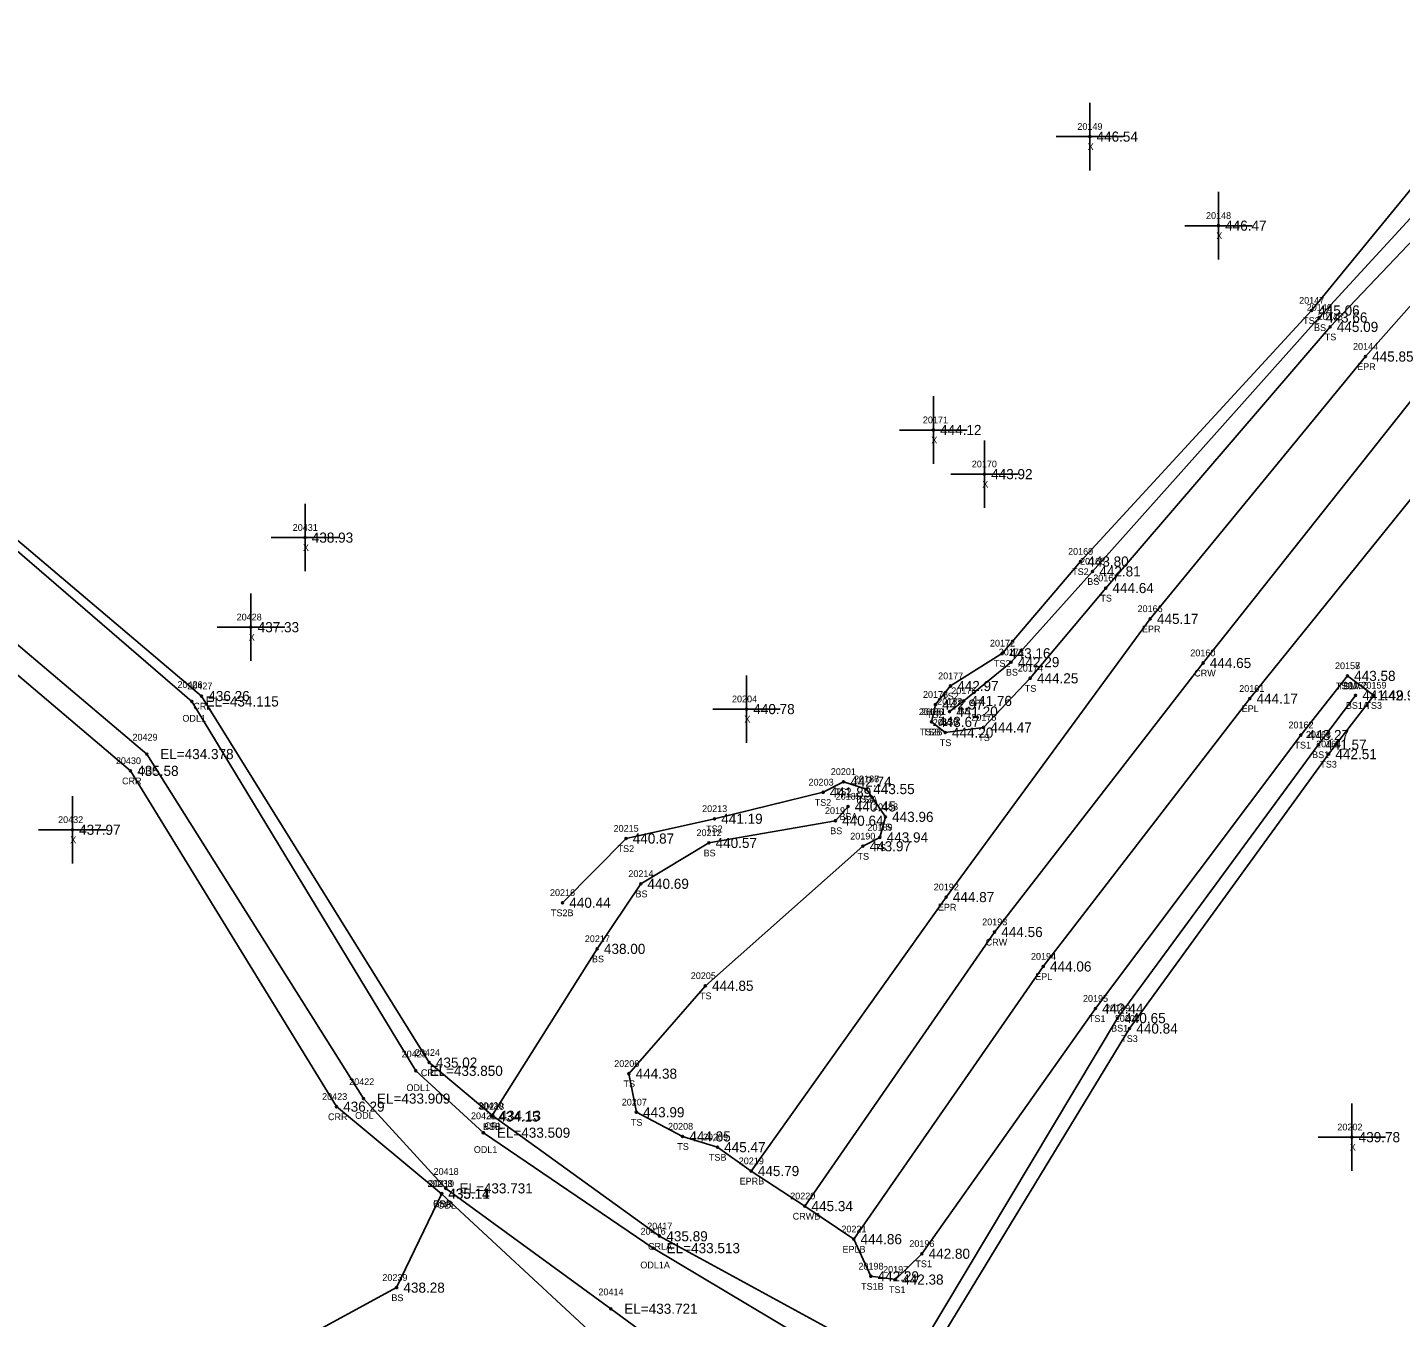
# Model space of a CAD drawing. Extents: x 1763022 to 1764007, y 824123 to 825394.
# Drawn here: x 1763375.9 to 1763579.5, y 824815.6 to 825006.9 of the extents above; entities that cross this region are included whole.
import ezdxf

# ---------------------------------------------------------------- set-up
doc = ezdxf.new("R2010")
doc.units = 0
for name, color, linetype in [('RD_DTM_BkLn1', 7, 'Continuous'), ('RD_DTM_BkLn2', 7, 'Continuous'), ('RD_DTM_BkLn_txCode', 7, 'Continuous'), ('RD_EX_H2O', 7, 'Continuous'), ('RD_EX_H2O_txCode', 7, 'Continuous'), ('RD_EX_Misc', 7, 'Continuous'), ('RD_EX_Misc_txCode', 7, 'Continuous'), ('RD_EX_Road', 7, 'Continuous'), ('RD_EX_Road_txCode', 7, 'Continuous'), ('RD_EX_TX_H2O_ELEV', 7, 'Continuous'), ('RD_EX_TX_Misc_ELEV', 7, 'Continuous'), ('RD_EX_TX_Road_ELEV', 7, 'Continuous'), ('RD_HC_Survey_ELEV', 7, 'Continuous'), ('RD_HC_Survey_txCode', 7, 'Continuous'), ('RD_SMD_Locator', 7, 'Continuous')]:
    doc.layers.add(name, color=color, linetype=linetype)

msp = doc.modelspace()

# ---------------------------------------------------------------- linework, layer by layer
at = {"layer": 'RD_DTM_BkLn1'}
msp.add_lwpolyline([(1763957.85, 825358.99), (1763889.22, 825284.86), (1763820.79, 825210.5), (1763751.37, 825137.44), (1763682.52, 825063.34), (1763613.99, 824989.62), (1763581.46, 824952.08), (1763550.2, 824912.66), (1763519.29, 824872.78), (1763491.16, 824832.15)], dxfattribs=at)
at = {"layer": 'RD_DTM_BkLn2'}
for points in [[(1763745.88, 825160.71), (1763743.95, 825161.45), (1763741.33, 825161.23), (1763734.19, 825151.51), (1763667.93, 825076.53), (1763598.29, 825004), (1763566.28, 824964.92), (1763532.04, 824927.7), (1763520.45, 824914.1), (1763512.76, 824909.25), (1763510.52, 824906.49), (1763509.94, 824903.93)], [(1763745.88, 825160.71), (1763746.84, 825156.51), (1763744.4, 825153.55), (1763739.17, 825147.71), (1763672.03, 825073.56), (1763603.55, 824998.75), (1763569.03, 824962.49), (1763535.77, 824923.77), (1763524.58, 824910.39), (1763517.67, 824903.1), (1763511.98, 824902.34), (1763509.94, 824903.93)], [(1763743.62, 825158.44), (1763736.6, 825149.65), (1763669.73, 825075.6), (1763601.09, 825000.55), (1763567.43, 824963.88), (1763533.82, 824926.24), (1763521.76, 824912.79), (1763514.73, 824907.04), (1763512.63, 824905.46)], [(1763571.6, 824910.75), (1763564.71, 824901.98), (1763534.24, 824861.43), (1763508.52, 824825.09), (1763504.6, 824821.26), (1763500.95, 824821.74)], [(1763571.6, 824910.75), (1763575.51, 824907.86), (1763568.82, 824899.15), (1763539.31, 824858.47), (1763506.93, 824805.24)], [(1763572.81, 824907.86), (1763567.31, 824900.56), (1763537.52, 824860.02), (1763505.47, 824806.41)], [(1763500.31, 824893.97), (1763496.89, 824895.06), (1763493.87, 824893.49), (1763477.78, 824889.57), (1763464.66, 824886.64), (1763455.25, 824877.12)], [(1763500.31, 824893.97), (1763503.11, 824889.85), (1763502.3, 824886.81), (1763499.77, 824885.49), (1763476.42, 824864.81), (1763465.09, 824851.78), (1763466.19, 824846.06), (1763473.05, 824842.48), (1763478.21, 824840.88)], [(1763497.57, 824891.4), (1763495.7, 824889.28), (1763476.94, 824885.99), (1763466.84, 824879.93), (1763460.39, 824870.28), (1763444.71, 824845.43)], [(1763437.34, 824834), (1763430.66, 824820.06), (1763415.77, 824811.96), (1763415.35, 824798.51), (1763416.46, 824790.14), (1763418.19, 824781.43), (1763421.71, 824775.16), (1763417.19, 824763.87), (1763415.91, 824751.32), (1763399.06, 824714.58), (1763377.03, 824668.46), (1763355.81, 824623.79), (1763331.1, 824577.59), (1763312.25, 824532.84), (1763306.13, 824522.15), (1763306.75, 824510.59), (1763289.07, 824468.95), (1763279.57, 824438.1), (1763246.06, 824343.25), (1763209.87, 824247.25), (1763175.28, 824154.06)]]:
    msp.add_lwpolyline(points, dxfattribs=at)
at = {"layer": 'RD_EX_H2O'}
for p, q in [((1763469.64, 824827.68), (1763496.79, 824812.85)), ((1763494.44, 824810.56), (1763468.68, 824825.92)), ((1763462.4, 824816.93), (1763486.08, 824799.65))]:
    msp.add_line(p, q, dxfattribs=at)
for points in [[(1763469.64, 824827.68), (1763444.91, 824845.55), (1763435.48, 824853.42), (1763401.74, 824907.76), (1763323.19, 824974.27), (1763226.75, 825015.18), (1763219.02, 825018.48), (1763206.39, 825014.43), (1763109.02, 824967.64), (1763091.9, 824957.32), (1763081.74, 824947.35), (1763046.14, 824865.15)], [(1763468.68, 824825.92), (1763443.51, 824843.03), (1763433.52, 824852.2), (1763400.31, 824906.96), (1763323, 824973.55), (1763227.11, 825012.29), (1763219.72, 825015.97), (1763207.36, 825012.11), (1763110.44, 824965.8), (1763093.36, 824955.52), (1763084.67, 824946.23), (1763047.83, 824863.38)], [(1763462.4, 824816.93), (1763437.96, 824834.78), (1763425.74, 824848.09), (1763393.61, 824899.16), (1763315.18, 824965.58), (1763227.67, 825003.59), (1763208.11, 824999.84), (1763110.65, 824956.1), (1763090.65, 824936.63), (1763063.26, 824852.64)], [(1763459.77, 824813.09), (1763437.3, 824833.98), (1763421.73, 824846.89), (1763391.2, 824896.67), (1763313.16, 824962.88), (1763227.9, 824997.52), (1763208.46, 824998.22), (1763114.18, 824952.92), (1763092.86, 824935.95), (1763064.35, 824852.13)]]:
    msp.add_lwpolyline(points, dxfattribs=at)
at = {"layer": 'RD_EX_Misc'}
for p, q in [((1763533.41, 824985.69), (1763533.41, 824995.69)), ((1763528.41, 824990.69), (1763538.41, 824990.69)), ((1763552.48, 824972.49), (1763552.48, 824982.49)), ((1763547.48, 824977.49), (1763557.48, 824977.49)), ((1763510.22, 824942.2), (1763510.22, 824952.2)), ((1763505.22, 824947.2), (1763515.22, 824947.2)), ((1763517.79, 824935.66), (1763517.79, 824945.66)), ((1763512.79, 824940.66), (1763522.79, 824940.66)), ((1763417.08, 824926.25), (1763417.08, 824936.25)), ((1763412.08, 824931.25), (1763422.08, 824931.25)), ((1763409.06, 824912.97), (1763409.06, 824922.97)), ((1763404.06, 824917.97), (1763414.06, 824917.97)), ((1763482.53, 824900.83), (1763482.53, 824910.83)), ((1763477.53, 824905.83), (1763487.53, 824905.83)), ((1763382.59, 824882.94), (1763382.59, 824892.94)), ((1763377.59, 824887.94), (1763387.59, 824887.94)), ((1763572.27, 824837.37), (1763572.27, 824847.37)), ((1763567.27, 824842.37), (1763577.27, 824842.37))]:
    msp.add_line(p, q, dxfattribs=at)
at = {"layer": 'RD_EX_Road'}
for points in [[(1763951.03, 825365.44), (1763882.12, 825291.59), (1763813.3, 825217.44), (1763784.22, 825184.64), (1763754.38, 825152.48), (1763744.67, 825142.84), (1763675.27, 825070.17), (1763607.46, 824995.53), (1763574.27, 824958.09), (1763542.37, 824919.2), (1763512.11, 824877.96), (1763483.2, 824837.35)], [(1763963.89, 825353.59), (1763895.68, 825279.08), (1763827.34, 825205.22), (1763758.38, 825131.33), (1763689.43, 825057.33), (1763653.53, 825018.75), (1763637.74, 825000.8), (1763620.71, 824983.81), (1763588.78, 824946.6), (1763557.13, 824907.38), (1763526.52, 824867.67), (1763498.43, 824827.25)], [(1763500.95, 824821.74), (1763498.43, 824827.25), (1763491.16, 824832.15), (1763483.2, 824837.35), (1763478.21, 824840.88)]]:
    msp.add_lwpolyline(points, dxfattribs=at)
at = {"layer": 'RD_SMD_Locator'}
for centre in [(1763533.41, 824990.69), (1763552.48, 824977.49), (1763566.28, 824964.92), (1763567.43, 824963.88), (1763569.03, 824962.49), (1763574.27, 824958.09), (1763510.22, 824947.2), (1763517.79, 824940.66), (1763417.08, 824931.25), (1763532.04, 824927.7), (1763533.82, 824926.24), (1763535.77, 824923.77), (1763409.06, 824917.97), (1763542.37, 824919.2), (1763520.45, 824914.1), (1763521.76, 824912.79), (1763550.2, 824912.66), (1763524.58, 824910.39), (1763571.6, 824910.75), (1763571.6, 824910.75), (1763401.74, 824907.76), (1763512.76, 824909.25), (1763572.81, 824907.86), (1763575.51, 824907.86), (1763400.31, 824906.96), (1763482.53, 824905.83), (1763510.52, 824906.49), (1763514.73, 824907.04), (1763557.13, 824907.38), (1763509.94, 824903.93), (1763509.94, 824903.93), (1763512.63, 824905.46), (1763511.98, 824902.34), (1763517.67, 824903.1), (1763564.71, 824901.98), (1763567.31, 824900.56), (1763393.61, 824899.16), (1763568.82, 824899.15), (1763391.2, 824896.67), (1763493.87, 824893.49), (1763496.89, 824895.06), (1763500.31, 824893.97), (1763500.31, 824893.97), (1763497.57, 824891.4), (1763477.78, 824889.57), (1763503.11, 824889.85), (1763382.59, 824887.94), (1763495.7, 824889.28), (1763464.66, 824886.64), (1763476.94, 824885.99), (1763499.77, 824885.49), (1763502.3, 824886.81), (1763466.84, 824879.93), (1763512.11, 824877.96), (1763455.25, 824877.12), (1763519.29, 824872.78), (1763460.39, 824870.28), (1763526.52, 824867.67), (1763476.42, 824864.81), (1763534.24, 824861.43), (1763537.52, 824860.02), (1763539.31, 824858.47), (1763435.48, 824853.42), (1763433.52, 824852.2), (1763465.09, 824851.78), (1763421.73, 824846.89), (1763425.74, 824848.09), (1763444.71, 824845.43), (1763444.91, 824845.55), (1763466.19, 824846.06), (1763443.51, 824843.03), (1763473.05, 824842.48), (1763478.21, 824840.88), (1763572.27, 824842.37), (1763483.2, 824837.35), (1763437.96, 824834.78), (1763437.3, 824833.98), (1763437.34, 824834), (1763491.16, 824832.15), (1763469.64, 824827.68), (1763498.43, 824827.25), (1763468.68, 824825.92), (1763508.52, 824825.09), (1763500.95, 824821.74), (1763504.6, 824821.26), (1763430.66, 824820.06), (1763462.4, 824816.93)]:
    msp.add_circle(centre, 0.15, dxfattribs=at)

# ---------------------------------------------------------------- texts
at = {"layer": 'RD_DTM_BkLn_txCode'}
for s, p in [('20147', (1763564.45, 824965.92)), ('20146', (1763565.57, 824964.88)), ('TS2', (1763565.04, 824962.92)), ('BS', (1763566.65, 824961.88)), ('20145', (1763567.2, 824963.49)), ('TS', (1763568.24, 824960.49)), ('20169', (1763530.19, 824928.7)), ('20168', (1763531.97, 824927.24)), ('TS2', (1763530.8, 824925.7)), ('BS', (1763533.04, 824924.24)), ('20167', (1763533.92, 824924.77)), ('TS', (1763534.98, 824921.77)), ('20172', (1763518.61, 824915.1)), ('20173', (1763519.92, 824913.79)), ('TS2', (1763519.2, 824912.1)), ('20174', (1763522.74, 824911.39)), ('20157', (1763569.76, 824911.75)), ('20158', (1763569.76, 824911.75)), ('20177', (1763510.93, 824910.25)), ('BS', (1763520.98, 824910.79)), ('20156', (1763570.95, 824908.86)), ('20159', (1763573.68, 824908.86)), ('20178', (1763508.68, 824907.49)), ('TS2', (1763511.52, 824907.25)), ('20176', (1763512.87, 824908.04)), ('TS', (1763523.78, 824908.39)), ('TS3A', (1763569.86, 824908.75)), ('TS1A', (1763570.15, 824908.75)), ('20180', (1763508.07, 824904.93)), ('20181', (1763508.39, 824904.93)), ('20182', (1763510.79, 824906.46)), ('BS', (1763513.95, 824905.04)), ('BS1A', (1763571.37, 824905.86)), ('TS3', (1763574.27, 824905.86)), ('TS2', (1763509.27, 824904.49)), ('20179', (1763510.14, 824903.34)), ('BSB', (1763511.37, 824903.46)), ('20175', (1763515.84, 824904.1)), ('20162', (1763562.86, 824902.98)), ('TS2B', (1763508.23, 824901.93)), ('TSB', (1763508.68, 824901.93)), ('TS', (1763516.88, 824901.1)), ('20163', (1763565.45, 824901.56)), ('TS', (1763511.18, 824900.34)), ('TS1', (1763563.75, 824899.98)), ('20164', (1763566.96, 824900.15)), ('BS1', (1763566.37, 824898.56)), ('TS3', (1763567.58, 824897.15)), ('20201', (1763495.02, 824896.06)), ('20186', (1763498.45, 824894.97)), ('20187', (1763498.47, 824894.97)), ('20203', (1763491.72, 824894.49)), ('TS2', (1763495.65, 824893.06)), ('20213', (1763475.94, 824890.57)), ('TS2', (1763492.63, 824891.49)), ('20185', (1763495.74, 824892.4)), ('TS2A', (1763498.57, 824891.97)), ('TSA', (1763499.02, 824891.97)), ('20188', (1763501.27, 824890.85)), ('20191', (1763494.15, 824890.28)), ('BSA', (1763496.3, 824889.4)), ('20215', (1763462.82, 824887.64)), ('20212', (1763475.11, 824886.99)), ('TS2', (1763476.53, 824887.57)), ('BS', (1763494.93, 824887.28)), ('20190', (1763497.9, 824886.49)), ('20189', (1763500.46, 824887.81)), ('TS', (1763502.31, 824887.85)), ('TS2', (1763463.41, 824884.64)), ('TS', (1763501.5, 824884.81)), ('BS', (1763476.16, 824883.99)), ('TS', (1763498.98, 824883.49)), ('20214', (1763465.01, 824880.93)), ('20216', (1763453.39, 824878.12)), ('BS', (1763466.06, 824877.93)), ('TS2B', (1763453.53, 824875.12)), ('20217', (1763458.55, 824871.28)), ('BS', (1763459.61, 824868.28)), ('20205', (1763474.26, 824865.81)), ('TS', (1763475.62, 824862.81)), ('20195', (1763532.4, 824862.43)), ('20199', (1763535.68, 824861.02)), ('TS1', (1763533.28, 824859.43)), ('BS1', (1763536.57, 824858.02)), ('20200', (1763537.11, 824859.47)), ('TS3', (1763538.07, 824856.47)), ('20206', (1763462.91, 824852.78)), ('TS', (1763464.29, 824849.78)), ('20218', (1763442.88, 824846.43)), ('20207', (1763464.03, 824847.06)), ('TS', (1763465.39, 824844.06)), ('BSB', (1763443.46, 824843.43)), ('20208', (1763470.89, 824843.48)), ('20209', (1763476.06, 824841.88)), ('TS', (1763472.26, 824840.48)), ('TSB', (1763476.95, 824838.88)), ('20238', (1763435.22, 824835)), ('BSA', (1763436.07, 824832)), ('20196', (1763506.66, 824826.09)), ('20198', (1763499.11, 824822.74)), ('20197', (1763502.77, 824822.26)), ('TS1', (1763507.56, 824823.09)), ('20239', (1763428.54, 824821.06)), ('TS1B', (1763499.51, 824819.74)), ('BS', (1763429.88, 824818.06)), ('TS1', (1763503.64, 824819.26))]:
    msp.add_text(s, height=1, dxfattribs=at).set_placement(p)
at = {"layer": 'RD_EX_H2O_txCode'}
for s, p in [('20426', (1763398.17, 824908.96)), ('20427', (1763399.63, 824908.76)), ('CRL', (1763400.52, 824905.76)), ('ODL1', (1763398.9, 824903.96)), ('20429', (1763391.5, 824901.16)), ('20430', (1763389.04, 824897.67)), ('CRR', (1763389.95, 824894.67)), ('ODL', (1763392.37, 824896.16)), ('20425', (1763431.4, 824854.2)), ('20424', (1763433.36, 824854.42)), ('20422', (1763423.62, 824850.09)), ('CRL', (1763434.25, 824851.42)), ('20423', (1763419.61, 824847.89)), ('ODL1', (1763432.11, 824849.2)), ('20420', (1763442.76, 824846.55)), ('CRR', (1763420.48, 824844.89)), ('ODL', (1763424.5, 824845.09)), ('20421', (1763441.68, 824845.03)), ('CRL', (1763443.68, 824843.55)), ('ODL1', (1763442.1, 824840.03)), ('20418', (1763436.13, 824836.78)), ('20419', (1763435.46, 824834.98)), ('CRR', (1763436.05, 824831.98)), ('ODL', (1763436.72, 824831.78)), ('20416', (1763466.82, 824827.92)), ('20417', (1763467.8, 824828.68)), ('CRLA', (1763467.92, 824825.68)), ('ODL1A', (1763466.78, 824822.92)), ('20414', (1763460.57, 824818.93))]:
    msp.add_text(s, height=1, dxfattribs=at).set_placement(p)
at = {"layer": 'RD_EX_Misc_txCode'}
for s, p in [('20149', (1763531.57, 824991.69)), ('X', (1763533.09, 824988.69)), ('20148', (1763550.64, 824978.49)), ('X', (1763552.16, 824975.49)), ('20171', (1763508.67, 824948.2)), ('X', (1763509.91, 824945.2)), ('20170', (1763515.92, 824941.66)), ('X', (1763517.48, 824938.66)), ('20431', (1763415.25, 824932.25)), ('X', (1763416.77, 824929.25)), ('20428', (1763406.94, 824918.97)), ('X', (1763408.74, 824915.97)), ('20204', (1763480.37, 824906.83)), ('X', (1763482.21, 824903.83)), ('20432', (1763380.47, 824888.94)), ('X', (1763382.27, 824885.94)), ('20202', (1763570.11, 824843.37)), ('X', (1763571.95, 824840.37))]:
    msp.add_text(s, height=1, dxfattribs=at).set_placement(p)
at = {"layer": 'RD_EX_Road_txCode'}
for s, p in [('20144', (1763572.43, 824959.09)), ('EPR', (1763573.04, 824956.09)), ('20166', (1763540.49, 824920.2)), ('EPR', (1763541.14, 824917.2)), ('20161', (1763555.56, 824908.38)), ('EPL', (1763555.93, 824905.38)), ('20192', (1763510.28, 824878.96)), ('EPR', (1763510.89, 824875.96)), ('20194', (1763524.69, 824868.67)), ('EPL', (1763525.32, 824865.67)), ('20219', (1763481.37, 824838.35)), ('EPRB', (1763481.5, 824835.35)), ('20221', (1763496.59, 824828.25)), ('EPLB', (1763496.75, 824825.25))]:
    msp.add_text(s, height=1, dxfattribs=at).set_placement(p)
at = {"layer": 'RD_EX_TX_H2O_ELEV'}
for s, p in [('436.26', (1763402.74, 824907.01)), ('EL=434.115', (1763402.31, 824906.21)), ('EL=434.378', (1763395.61, 824898.41)), ('435.58', (1763392.2, 824895.92)), ('EL=433.850', (1763435.52, 824851.45)), ('435.02', (1763436.48, 824852.67)), ('EL=433.909', (1763427.74, 824847.34)), ('436.29', (1763422.73, 824846.14)), ('434.13', (1763445.91, 824844.8)), ('EL=433.509', (1763445.51, 824842.28)), ('435.14', (1763438.3, 824833.23)), ('EL=433.731', (1763439.96, 824834.03)), ('435.89', (1763470.64, 824826.93)), ('EL=433.513', (1763470.68, 824825.17)), ('EL=433.721', (1763464.4, 824816.18))]:
    msp.add_text(s, height=1.5, dxfattribs=at).set_placement(p)
at = {"layer": 'RD_EX_TX_Misc_ELEV'}
for s, p in [('446.54', (1763534.41, 824989.94)), ('446.47', (1763553.48, 824976.74)), ('445.06', (1763567.28, 824964.17)), ('443.66', (1763568.43, 824963.13)), ('445.09', (1763570.03, 824961.74)), ('444.12', (1763511.22, 824946.45)), ('443.92', (1763518.79, 824939.91)), ('438.93', (1763418.08, 824930.5)), ('443.80', (1763533.04, 824926.95)), ('442.81', (1763534.82, 824925.49)), ('444.64', (1763536.77, 824923.02)), ('437.33', (1763410.06, 824917.22)), ('443.16', (1763521.45, 824913.35)), ('442.29', (1763522.76, 824912.04)), ('442.97', (1763513.76, 824908.5)), ('444.25', (1763525.58, 824909.64)), ('443.58', (1763572.6, 824910)), ('443.58', (1763572.6, 824910)), ('441.76', (1763515.73, 824906.29)), ('441.49', (1763573.81, 824907.11)), ('442.90', (1763576.51, 824907.11)), ('440.78', (1763483.53, 824905.08)), ('442.97', (1763511.52, 824905.74)), ('441.20', (1763513.63, 824904.71)), ('443.67', (1763510.94, 824903.18)), ('443.67', (1763510.94, 824903.18)), ('444.47', (1763518.67, 824902.35)), ('444.20', (1763512.98, 824901.59)), ('443.27', (1763565.71, 824901.23)), ('441.57', (1763568.31, 824899.81)), ('442.51', (1763569.82, 824898.4)), ('442.74', (1763497.89, 824894.31)), ('441.89', (1763494.87, 824892.74)), ('443.55', (1763501.31, 824893.22)), ('443.55', (1763501.31, 824893.22)), ('440.45', (1763498.57, 824890.65)), ('441.19', (1763478.78, 824888.82)), ('440.64', (1763496.7, 824888.53)), ('443.96', (1763504.11, 824889.1)), ('437.97', (1763383.59, 824887.19)), ('443.94', (1763503.3, 824886.06)), ('440.87', (1763465.66, 824885.89)), ('440.57', (1763477.94, 824885.24)), ('443.97', (1763500.77, 824884.74)), ('440.69', (1763467.84, 824879.18)), ('440.44', (1763456.25, 824876.37)), ('438.00', (1763461.39, 824869.53)), ('444.85', (1763477.42, 824864.06)), ('442.44', (1763535.24, 824860.68)), ('440.65', (1763538.52, 824859.27)), ('440.84', (1763540.31, 824857.72)), ('444.38', (1763466.09, 824851.03)), ('443.99', (1763467.19, 824845.31)), ('434.15', (1763445.71, 824844.68)), ('444.85', (1763474.05, 824841.73)), ('439.78', (1763573.27, 824841.62)), ('445.47', (1763479.21, 824840.13)), ('435.11', (1763438.34, 824833.25)), ('442.80', (1763509.52, 824824.34)), ('442.29', (1763501.95, 824820.99)), ('438.28', (1763431.66, 824819.31)), ('442.38', (1763505.6, 824820.51))]:
    msp.add_text(s, height=1.5, dxfattribs=at).set_placement(p)
at = {"layer": 'RD_EX_TX_Road_ELEV'}
for s, p in [('445.85', (1763575.27, 824957.34)), ('445.17', (1763543.37, 824918.45)), ('444.17', (1763558.13, 824906.63)), ('444.87', (1763513.11, 824877.21)), ('444.06', (1763527.52, 824866.92)), ('445.79', (1763484.2, 824836.6)), ('444.86', (1763499.43, 824826.5))]:
    msp.add_text(s, height=1.5, dxfattribs=at).set_placement(p)
at = {"layer": 'RD_HC_Survey_ELEV'}
for s, p in [('444.65', (1763551.2, 824911.91)), ('444.56', (1763520.29, 824872.03)), ('445.34', (1763492.16, 824831.4))]:
    msp.add_text(s, height=1.5, dxfattribs=at).set_placement(p)
at = {"layer": 'RD_HC_Survey_txCode'}
for s, p in [('20160', (1763548.31, 824913.66)), ('CRW', (1763548.89, 824910.66)), ('20193', (1763517.46, 824873.78)), ('CRW', (1763517.98, 824870.78)), ('20220', (1763489, 824833.15)), ('CRWB', (1763489.37, 824830.15))]:
    msp.add_text(s, height=1, dxfattribs=at).set_placement(p)

doc.saveas('drawing.dxf')
